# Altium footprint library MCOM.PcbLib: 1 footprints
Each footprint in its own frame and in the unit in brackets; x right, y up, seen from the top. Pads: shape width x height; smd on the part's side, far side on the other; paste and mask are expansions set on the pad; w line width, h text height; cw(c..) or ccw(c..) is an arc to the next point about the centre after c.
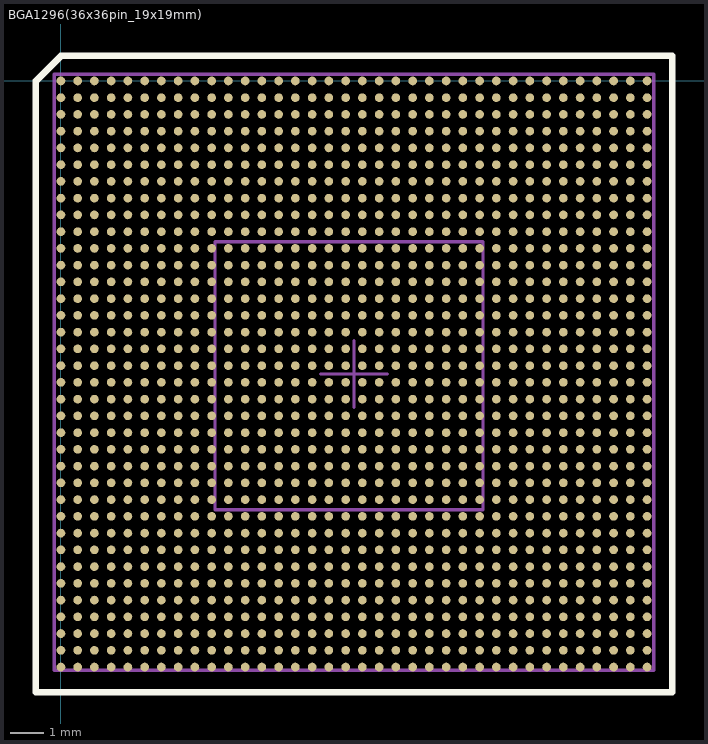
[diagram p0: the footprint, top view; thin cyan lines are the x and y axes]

## BGA1296(36x36pin_19x19mm) [mm]
height 2.5
pads (1296):
  round 0.26 smd mask+0.06: A1(0,0) A2(0.5,0) A3(1,0) A4(1.5,0) A5(2,0) A6(2.5,0) A7(3,0) A8(3.5,0) A9(4,0) A10(4.5,0) A11(5,0) A12(5.5,0) A13(6,0) A14(6.5,0) A15(7,0) A16(7.5,0) A17(8,0) A18(8.5,0) A19(9,0) A20(9.5,0) A21(10,0) A22(10.5,0) A23(11,0) A24(11.5,0) A25(12,0) A26(12.5,0) A27(13,0) A28(13.5,0) A29(14,0) A30(14.5,0) A31(15,0) A32(15.5,0) A33(16,0) A34(16.5,0) A35(17,0) A36(17.5,0) AA1(0,-10) AA2(0.5,-10) AA3(1,-10) AA4(1.5,-10) AA5(2,-10) AA6(2.5,-10) AA7(3,-10) AA8(3.5,-10) AA9(4,-10) AA10(4.5,-10) AA11(5,-10) AA12(5.5,-10) AA13(6,-10) AA14(6.5,-10) AA15(7,-10) AA16(7.5,-10) AA17(8,-10) AA18(8.5,-10) AA19(9,-10) AA20(9.5,-10) AA21(10,-10) AA22(10.5,-10) AA23(11,-10) AA24(11.5,-10) AA25(12,-10) AA26(12.5,-10) AA27(13,-10) AA28(13.5,-10) AA29(14,-10) AA30(14.5,-10) AA31(15,-10) AA32(15.5,-10) AA33(16,-10) AA34(16.5,-10) AA35(17,-10) AA36(17.5,-10) AB1(0,-10.5) AB2(0.5,-10.5) AB3(1,-10.5) AB4(1.5,-10.5) AB5(2,-10.5) AB6(2.5,-10.5) AB7(3,-10.5) AB8(3.5,-10.5) AB9(4,-10.5) AB10(4.5,-10.5) AB11(5,-10.5) AB12(5.5,-10.5) AB13(6,-10.5) AB14(6.5,-10.5) AB15(7,-10.5) AB16(7.5,-10.5) AB17(8,-10.5) AB18(8.5,-10.5) AB19(9,-10.5) AB20(9.5,-10.5) AB21(10,-10.5) AB22(10.5,-10.5) AB23(11,-10.5) AB24(11.5,-10.5) AB25(12,-10.5) AB26(12.5,-10.5) AB27(13,-10.5) AB28(13.5,-10.5) AB29(14,-10.5) AB30(14.5,-10.5) AB31(15,-10.5) AB32(15.5,-10.5) AB33(16,-10.5) AB34(16.5,-10.5) AB35(17,-10.5) AB36(17.5,-10.5) AC1(0,-11) AC2(0.5,-11) AC3(1,-11) AC4(1.5,-11) AC5(2,-11) AC6(2.5,-11) AC7(3,-11) AC8(3.5,-11) AC9(4,-11) AC10(4.5,-11) AC11(5,-11) AC12(5.5,-11) AC13(6,-11) AC14(6.5,-11) AC15(7,-11) AC16(7.5,-11) AC17(8,-11) AC18(8.5,-11) AC19(9,-11) AC20(9.5,-11) AC21(10,-11) AC22(10.5,-11) AC23(11,-11) AC24(11.5,-11) AC25(12,-11) AC26(12.5,-11) AC27(13,-11) AC28(13.5,-11) AC29(14,-11) AC30(14.5,-11) AC31(15,-11) AC32(15.5,-11) AC33(16,-11) AC34(16.5,-11) AC35(17,-11) AC36(17.5,-11) AD1(0,-11.5) AD2(0.5,-11.5) AD3(1,-11.5) AD4(1.5,-11.5) AD5(2,-11.5) AD6(2.5,-11.5) AD7(3,-11.5) AD8(3.5,-11.5) AD9(4,-11.5) AD10(4.5,-11.5) AD11(5,-11.5) AD12(5.5,-11.5) AD13(6,-11.5) AD14(6.5,-11.5) AD15(7,-11.5) AD16(7.5,-11.5) AD17(8,-11.5) AD18(8.5,-11.5) AD19(9,-11.5) AD20(9.5,-11.5) AD21(10,-11.5) AD22(10.5,-11.5) AD23(11,-11.5) AD24(11.5,-11.5) AD25(12,-11.5) AD26(12.5,-11.5) AD27(13,-11.5) AD28(13.5,-11.5) AD29(14,-11.5) AD30(14.5,-11.5) AD31(15,-11.5) AD32(15.5,-11.5) AD33(16,-11.5) AD34(16.5,-11.5) AD35(17,-11.5) AD36(17.5,-11.5) AE1(0,-12) AE2(0.5,-12) AE3(1,-12) AE4(1.5,-12) AE5(2,-12) AE6(2.5,-12) AE7(3,-12) AE8(3.5,-12) AE9(4,-12) AE10(4.5,-12) AE11(5,-12) AE12(5.5,-12) AE13(6,-12) AE14(6.5,-12) AE15(7,-12) AE16(7.5,-12) AE17(8,-12) AE18(8.5,-12) AE19(9,-12) AE20(9.5,-12) AE21(10,-12) AE22(10.5,-12) AE23(11,-12) AE24(11.5,-12) AE25(12,-12) AE26(12.5,-12) AE27(13,-12) AE28(13.5,-12) AE29(14,-12) AE30(14.5,-12) AE31(15,-12) AE32(15.5,-12) AE33(16,-12) AE34(16.5,-12) AE35(17,-12) AE36(17.5,-12) AF1(0,-12.5) AF2(0.5,-12.5) AF3(1,-12.5) AF4(1.5,-12.5) AF5(2,-12.5) AF6(2.5,-12.5) AF7(3,-12.5) AF8(3.5,-12.5) AF9(4,-12.5) AF10(4.5,-12.5) AF11(5,-12.5) AF12(5.5,-12.5) AF13(6,-12.5) AF14(6.5,-12.5) AF15(7,-12.5) AF16(7.5,-12.5) AF17(8,-12.5) AF18(8.5,-12.5) AF19(9,-12.5) AF20(9.5,-12.5) AF21(10,-12.5) AF22(10.5,-12.5) AF23(11,-12.5) AF24(11.5,-12.5) AF25(12,-12.5) AF26(12.5,-12.5) AF27(13,-12.5) AF28(13.5,-12.5) AF29(14,-12.5) AF30(14.5,-12.5) AF31(15,-12.5) AF32(15.5,-12.5) AF33(16,-12.5) AF34(16.5,-12.5) AF35(17,-12.5) AF36(17.5,-12.5) AG1(0,-13) AG2(0.5,-13) AG3(1,-13) AG4(1.5,-13) AG5(2,-13) AG6(2.5,-13) AG7(3,-13) AG8(3.5,-13) AG9(4,-13) AG10(4.5,-13) AG11(5,-13) AG12(5.5,-13) AG13(6,-13) AG14(6.5,-13) AG15(7,-13) AG16(7.5,-13) AG17(8,-13) AG18(8.5,-13) AG19(9,-13) AG20(9.5,-13) AG21(10,-13) AG22(10.5,-13) AG23(11,-13) AG24(11.5,-13) AG25(12,-13) AG26(12.5,-13) AG27(13,-13) AG28(13.5,-13) AG29(14,-13) AG30(14.5,-13) AG31(15,-13) AG32(15.5,-13) AG33(16,-13) AG34(16.5,-13) AG35(17,-13) AG36(17.5,-13) AH1(0,-13.5) AH2(0.5,-13.5) AH3(1,-13.5) AH4(1.5,-13.5) AH5(2,-13.5) AH6(2.5,-13.5) AH7(3,-13.5) AH8(3.5,-13.5) AH9(4,-13.5) AH10(4.5,-13.5) AH11(5,-13.5) AH12(5.5,-13.5) AH13(6,-13.5) AH14(6.5,-13.5) AH15(7,-13.5) AH16(7.5,-13.5) AH17(8,-13.5) AH18(8.5,-13.5) AH19(9,-13.5) AH20(9.5,-13.5) AH21(10,-13.5) AH22(10.5,-13.5) AH23(11,-13.5) AH24(11.5,-13.5) AH25(12,-13.5) AH26(12.5,-13.5) AH27(13,-13.5) AH28(13.5,-13.5) AH29(14,-13.5) AH30(14.5,-13.5) AH31(15,-13.5) AH32(15.5,-13.5) AH33(16,-13.5) AH34(16.5,-13.5) AH35(17,-13.5) AH36(17.5,-13.5) AJ1(0,-14) AJ2(0.5,-14) AJ3(1,-14) AJ4(1.5,-14) AJ5(2,-14) AJ6(2.5,-14) AJ7(3,-14) AJ8(3.5,-14) AJ9(4,-14) AJ10(4.5,-14) AJ11(5,-14) AJ12(5.5,-14) AJ13(6,-14) AJ14(6.5,-14) AJ15(7,-14) AJ16(7.5,-14) AJ17(8,-14) AJ18(8.5,-14) AJ19(9,-14) AJ20(9.5,-14) AJ21(10,-14) AJ22(10.5,-14) AJ23(11,-14) AJ24(11.5,-14) AJ25(12,-14) AJ26(12.5,-14) AJ27(13,-14) AJ28(13.5,-14) AJ29(14,-14) AJ30(14.5,-14) AJ31(15,-14) AJ32(15.5,-14) AJ33(16,-14) AJ34(16.5,-14) AJ35(17,-14) AJ36(17.5,-14) AK1(0,-14.5) AK2(0.5,-14.5) AK3(1,-14.5) AK4(1.5,-14.5) AK5(2,-14.5) AK6(2.5,-14.5) AK7(3,-14.5) AK8(3.5,-14.5) AK9(4,-14.5) AK10(4.5,-14.5) AK11(5,-14.5) AK12(5.5,-14.5) AK13(6,-14.5) AK14(6.5,-14.5) AK15(7,-14.5) AK16(7.5,-14.5) AK17(8,-14.5) AK18(8.5,-14.5) AK19(9,-14.5) AK20(9.5,-14.5) AK21(10,-14.5) AK22(10.5,-14.5) AK23(11,-14.5) AK24(11.5,-14.5) AK25(12,-14.5) AK26(12.5,-14.5) AK27(13,-14.5) AK28(13.5,-14.5) AK29(14,-14.5) AK30(14.5,-14.5) AK31(15,-14.5) AK32(15.5,-14.5) AK33(16,-14.5) AK34(16.5,-14.5) AK35(17,-14.5) AK36(17.5,-14.5) AL1(0,-15) AL2(0.5,-15) AL3(1,-15) AL4(1.5,-15) AL5(2,-15) AL6(2.5,-15) AL7(3,-15) AL8(3.5,-15) AL9(4,-15) AL10(4.5,-15) AL11(5,-15) AL12(5.5,-15) AL13(6,-15) AL14(6.5,-15) AL15(7,-15) AL16(7.5,-15) AL17(8,-15) AL18(8.5,-15) AL19(9,-15) AL20(9.5,-15) AL21(10,-15) AL22(10.5,-15) AL23(11,-15) AL24(11.5,-15) AL25(12,-15) AL26(12.5,-15) AL27(13,-15) AL28(13.5,-15) AL29(14,-15) AL30(14.5,-15) AL31(15,-15) AL32(15.5,-15) AL33(16,-15) AL34(16.5,-15) AL35(17,-15) AL36(17.5,-15) AM1(0,-15.5) AM2(0.5,-15.5) AM3(1,-15.5) AM4(1.5,-15.5) AM5(2,-15.5) AM6(2.5,-15.5) AM7(3,-15.5) AM8(3.5,-15.5) AM9(4,-15.5) AM10(4.5,-15.5) AM11(5,-15.5) AM12(5.5,-15.5) AM13(6,-15.5) AM14(6.5,-15.5) AM15(7,-15.5) AM16(7.5,-15.5) AM17(8,-15.5) AM18(8.5,-15.5) AM19(9,-15.5) AM20(9.5,-15.5) AM21(10,-15.5) AM22(10.5,-15.5) AM23(11,-15.5) AM24(11.5,-15.5) AM25(12,-15.5) AM26(12.5,-15.5) AM27(13,-15.5) AM28(13.5,-15.5) AM29(14,-15.5) AM30(14.5,-15.5) AM31(15,-15.5) AM32(15.5,-15.5) AM33(16,-15.5) AM34(16.5,-15.5) AM35(17,-15.5) AM36(17.5,-15.5) AN1(0,-16) AN2(0.5,-16) AN3(1,-16) AN4(1.5,-16) AN5(2,-16) AN6(2.5,-16) AN7(3,-16) AN8(3.5,-16) AN9(4,-16) AN10(4.5,-16) AN11(5,-16) AN12(5.5,-16) AN13(6,-16) AN14(6.5,-16) AN15(7,-16) AN16(7.5,-16) AN17(8,-16) AN18(8.5,-16) AN19(9,-16) AN20(9.5,-16) AN21(10,-16) AN22(10.5,-16) AN23(11,-16) AN24(11.5,-16) AN25(12,-16) AN26(12.5,-16) AN27(13,-16) AN28(13.5,-16) AN29(14,-16) AN30(14.5,-16) AN31(15,-16) AN32(15.5,-16) AN33(16,-16) AN34(16.5,-16) AN35(17,-16) AN36(17.5,-16) AP1(0,-16.5) AP2(0.5,-16.5) AP3(1,-16.5) AP4(1.5,-16.5) AP5(2,-16.5) AP6(2.5,-16.5) AP7(3,-16.5) AP8(3.5,-16.5) AP9(4,-16.5) AP10(4.5,-16.5) AP11(5,-16.5) AP12(5.5,-16.5) AP13(6,-16.5) AP14(6.5,-16.5) AP15(7,-16.5) AP16(7.5,-16.5) AP17(8,-16.5) AP18(8.5,-16.5) AP19(9,-16.5) AP20(9.5,-16.5) AP21(10,-16.5) AP22(10.5,-16.5) AP23(11,-16.5) AP24(11.5,-16.5) AP25(12,-16.5) AP26(12.5,-16.5) AP27(13,-16.5) AP28(13.5,-16.5) AP29(14,-16.5) AP30(14.5,-16.5) AP31(15,-16.5) AP32(15.5,-16.5) AP33(16,-16.5) AP34(16.5,-16.5) AP35(17,-16.5) AP36(17.5,-16.5) AR1(0,-17) AR2(0.5,-17) AR3(1,-17) AR4(1.5,-17) AR5(2,-17) AR6(2.5,-17) AR7(3,-17) AR8(3.5,-17) AR9(4,-17) AR10(4.5,-17) AR11(5,-17) AR12(5.5,-17) AR13(6,-17) AR14(6.5,-17) AR15(7,-17) AR16(7.5,-17) AR17(8,-17) AR18(8.5,-17) AR19(9,-17) AR20(9.5,-17) AR21(10,-17) AR22(10.5,-17) AR23(11,-17) AR24(11.5,-17) AR25(12,-17) AR26(12.5,-17) AR27(13,-17) AR28(13.5,-17) AR29(14,-17) AR30(14.5,-17) AR31(15,-17) AR32(15.5,-17) AR33(16,-17) AR34(16.5,-17) AR35(17,-17) AR36(17.5,-17) AT1(0,-17.5) AT2(0.5,-17.5) AT3(1,-17.5) AT4(1.5,-17.5) AT5(2,-17.5) AT6(2.5,-17.5) AT7(3,-17.5) AT8(3.5,-17.5) AT9(4,-17.5) AT10(4.5,-17.5) AT11(5,-17.5) AT12(5.5,-17.5) AT13(6,-17.5) AT14(6.5,-17.5) AT15(7,-17.5) AT16(7.5,-17.5) AT17(8,-17.5) AT18(8.5,-17.5) AT19(9,-17.5) AT20(9.5,-17.5) AT21(10,-17.5) AT22(10.5,-17.5) AT23(11,-17.5) AT24(11.5,-17.5) AT25(12,-17.5) AT26(12.5,-17.5) AT27(13,-17.5) AT28(13.5,-17.5) AT29(14,-17.5) AT30(14.5,-17.5) AT31(15,-17.5) AT32(15.5,-17.5) AT33(16,-17.5) AT34(16.5,-17.5) AT35(17,-17.5) AT36(17.5,-17.5) B1(0,-0.5) B2(0.5,-0.5) B3(1,-0.5) B4(1.5,-0.5) B5(2,-0.5) B6(2.5,-0.5) B7(3,-0.5) B8(3.5,-0.5) B9(4,-0.5) B10(4.5,-0.5) B11(5,-0.5) B12(5.5,-0.5) B13(6,-0.5) B14(6.5,-0.5) B15(7,-0.5) B16(7.5,-0.5) B17(8,-0.5) B18(8.5,-0.5) B19(9,-0.5) B20(9.5,-0.5) B21(10,-0.5) B22(10.5,-0.5) B23(11,-0.5) B24(11.5,-0.5) B25(12,-0.5) B26(12.5,-0.5) B27(13,-0.5) B28(13.5,-0.5) B29(14,-0.5) B30(14.5,-0.5) B31(15,-0.5) B32(15.5,-0.5) B33(16,-0.5) B34(16.5,-0.5) B35(17,-0.5) B36(17.5,-0.5) C1(0,-1) C2(0.5,-1) C3(1,-1) C4(1.5,-1) C5(2,-1) C6(2.5,-1) C7(3,-1) C8(3.5,-1) C9(4,-1) C10(4.5,-1) C11(5,-1) C12(5.5,-1) C13(6,-1) C14(6.5,-1) C15(7,-1) C16(7.5,-1) C17(8,-1) C18(8.5,-1) C19(9,-1) C20(9.5,-1) C21(10,-1) C22(10.5,-1) C23(11,-1) C24(11.5,-1) C25(12,-1) C26(12.5,-1) C27(13,-1) C28(13.5,-1) C29(14,-1) C30(14.5,-1) C31(15,-1) C32(15.5,-1) C33(16,-1) C34(16.5,-1) C35(17,-1) C36(17.5,-1) D1(0,-1.5) D2(0.5,-1.5) D3(1,-1.5) D4(1.5,-1.5) D5(2,-1.5) D6(2.5,-1.5) D7(3,-1.5) D8(3.5,-1.5) D9(4,-1.5) D10(4.5,-1.5) D11(5,-1.5) D12(5.5,-1.5) D13(6,-1.5) D14(6.5,-1.5) D15(7,-1.5) D16(7.5,-1.5) D17(8,-1.5) D18(8.5,-1.5) D19(9,-1.5) D20(9.5,-1.5) D21(10,-1.5) D22(10.5,-1.5) D23(11,-1.5) D24(11.5,-1.5) D25(12,-1.5) D26(12.5,-1.5) D27(13,-1.5) D28(13.5,-1.5) D29(14,-1.5) D30(14.5,-1.5) D31(15,-1.5) D32(15.5,-1.5) D33(16,-1.5) D34(16.5,-1.5) D35(17,-1.5) D36(17.5,-1.5) E1(0,-2) E2(0.5,-2) E3(1,-2) E4(1.5,-2) E5(2,-2) E6(2.5,-2) E7(3,-2) E8(3.5,-2) E9(4,-2) E10(4.5,-2) E11(5,-2) E12(5.5,-2) E13(6,-2) E14(6.5,-2) E15(7,-2) E16(7.5,-2) E17(8,-2) E18(8.5,-2) E19(9,-2) E20(9.5,-2) E21(10,-2) E22(10.5,-2) E23(11,-2) E24(11.5,-2) E25(12,-2) E26(12.5,-2) E27(13,-2) E28(13.5,-2) E29(14,-2) E30(14.5,-2) E31(15,-2) E32(15.5,-2) E33(16,-2) E34(16.5,-2) E35(17,-2) E36(17.5,-2) F1(0,-2.5) F2(0.5,-2.5) F3(1,-2.5) F4(1.5,-2.5) F5(2,-2.5) F6(2.5,-2.5) F7(3,-2.5) F8(3.5,-2.5) F9(4,-2.5) F10(4.5,-2.5) F11(5,-2.5) F12(5.5,-2.5) F13(6,-2.5) F14(6.5,-2.5) F15(7,-2.5) F16(7.5,-2.5) F17(8,-2.5) F18(8.5,-2.5) F19(9,-2.5) F20(9.5,-2.5) F21(10,-2.5) F22(10.5,-2.5) F23(11,-2.5) F24(11.5,-2.5) F25(12,-2.5) F26(12.5,-2.5) F27(13,-2.5) F28(13.5,-2.5) F29(14,-2.5) F30(14.5,-2.5) F31(15,-2.5) F32(15.5,-2.5) F33(16,-2.5) F34(16.5,-2.5) F35(17,-2.5) F36(17.5,-2.5) G1(0,-3) G2(0.5,-3) G3(1,-3) G4(1.5,-3) G5(2,-3) G6(2.5,-3) G7(3,-3) G8(3.5,-3) G9(4,-3) G10(4.5,-3) G11(5,-3) G12(5.5,-3) G13(6,-3) G14(6.5,-3) G15(7,-3) G16(7.5,-3) G17(8,-3) G18(8.5,-3) G19(9,-3) G20(9.5,-3) G21(10,-3) G22(10.5,-3) G23(11,-3) G24(11.5,-3) G25(12,-3) G26(12.5,-3) G27(13,-3) G28(13.5,-3) G29(14,-3) G30(14.5,-3) G31(15,-3) G32(15.5,-3) G33(16,-3) G34(16.5,-3) G35(17,-3) G36(17.5,-3) H1(0,-3.5) H2(0.5,-3.5) H3(1,-3.5) H4(1.5,-3.5) H5(2,-3.5) H6(2.5,-3.5) H7(3,-3.5) H8(3.5,-3.5) H9(4,-3.5) H10(4.5,-3.5) H11(5,-3.5) H12(5.5,-3.5) H13(6,-3.5) H14(6.5,-3.5) H15(7,-3.5) H16(7.5,-3.5) H17(8,-3.5) H18(8.5,-3.5) H19(9,-3.5) H20(9.5,-3.5) H21(10,-3.5) H22(10.5,-3.5) H23(11,-3.5) H24(11.5,-3.5) H25(12,-3.5) H26(12.5,-3.5) H27(13,-3.5) H28(13.5,-3.5) H29(14,-3.5) H30(14.5,-3.5) H31(15,-3.5) H32(15.5,-3.5) H33(16,-3.5) H34(16.5,-3.5) H35(17,-3.5) H36(17.5,-3.5) J1(0,-4) J2(0.5,-4) J3(1,-4) J4(1.5,-4) J5(2,-4) J6(2.5,-4) J7(3,-4) J8(3.5,-4) J9(4,-4) J10(4.5,-4) J11(5,-4) J12(5.5,-4) J13(6,-4) J14(6.5,-4) J15(7,-4) J16(7.5,-4) J17(8,-4) J18(8.5,-4) J19(9,-4) J20(9.5,-4) J21(10,-4) J22(10.5,-4) J23(11,-4) J24(11.5,-4) J25(12,-4) J26(12.5,-4) J27(13,-4) J28(13.5,-4) J29(14,-4) J30(14.5,-4) J31(15,-4) J32(15.5,-4) J33(16,-4) J34(16.5,-4) J35(17,-4) J36(17.5,-4) K1(0,-4.5) K2(0.5,-4.5) K3(1,-4.5) K4(1.5,-4.5) K5(2,-4.5) K6(2.5,-4.5) K7(3,-4.5) K8(3.5,-4.5) K9(4,-4.5) K10(4.5,-4.5) K11(5,-4.5) K12(5.5,-4.5) K13(6,-4.5) K14(6.5,-4.5) K15(7,-4.5) K16(7.5,-4.5) K17(8,-4.5) K18(8.5,-4.5) K19(9,-4.5) K20(9.5,-4.5) K21(10,-4.5) K22(10.5,-4.5) K23(11,-4.5) K24(11.5,-4.5) K25(12,-4.5) K26(12.5,-4.5) K27(13,-4.5) K28(13.5,-4.5) K29(14,-4.5) K30(14.5,-4.5) K31(15,-4.5) K32(15.5,-4.5) K33(16,-4.5) K34(16.5,-4.5) K35(17,-4.5) K36(17.5,-4.5) L1(0,-5) L2(0.5,-5) L3(1,-5) L4(1.5,-5) L5(2,-5) L6(2.5,-5) L7(3,-5) L8(3.5,-5) L9(4,-5) L10(4.5,-5) L11(5,-5) L12(5.5,-5) L13(6,-5) L14(6.5,-5) L15(7,-5) L16(7.5,-5) L17(8,-5) L18(8.5,-5) L19(9,-5) L20(9.5,-5) L21(10,-5) L22(10.5,-5) L23(11,-5) L24(11.5,-5) L25(12,-5) L26(12.5,-5) L27(13,-5) L28(13.5,-5) L29(14,-5) L30(14.5,-5) L31(15,-5) L32(15.5,-5) L33(16,-5) L34(16.5,-5) L35(17,-5) L36(17.5,-5) M1(0,-5.5) M2(0.5,-5.5) M3(1,-5.5) M4(1.5,-5.5) M5(2,-5.5) M6(2.5,-5.5) M7(3,-5.5) M8(3.5,-5.5) M9(4,-5.5) M10(4.5,-5.5) M11(5,-5.5) M12(5.5,-5.5) M13(6,-5.5) M14(6.5,-5.5) M15(7,-5.5) M16(7.5,-5.5) M17(8,-5.5) M18(8.5,-5.5) M19(9,-5.5) M20(9.5,-5.5) M21(10,-5.5) M22(10.5,-5.5) M23(11,-5.5) M24(11.5,-5.5) M25(12,-5.5) M26(12.5,-5.5) M27(13,-5.5) M28(13.5,-5.5) M29(14,-5.5) M30(14.5,-5.5) M31(15,-5.5) M32(15.5,-5.5) M33(16,-5.5) M34(16.5,-5.5) M35(17,-5.5) M36(17.5,-5.5) N1(0,-6) N2(0.5,-6) N3(1,-6) N4(1.5,-6) N5(2,-6) N6(2.5,-6) N7(3,-6) N8(3.5,-6) N9(4,-6) N10(4.5,-6) N11(5,-6) N12(5.5,-6) N13(6,-6) N14(6.5,-6) N15(7,-6) N16(7.5,-6) N17(8,-6) N18(8.5,-6) N19(9,-6) N20(9.5,-6) N21(10,-6) N22(10.5,-6) N23(11,-6) N24(11.5,-6) N25(12,-6) N26(12.5,-6) N27(13,-6) N28(13.5,-6) N29(14,-6) N30(14.5,-6) N31(15,-6) N32(15.5,-6) N33(16,-6) N34(16.5,-6) N35(17,-6) N36(17.5,-6) P1(0,-6.5) P2(0.5,-6.5) P3(1,-6.5) P4(1.5,-6.5) P5(2,-6.5) P6(2.5,-6.5) P7(3,-6.5) P8(3.5,-6.5) P9(4,-6.5) P10(4.5,-6.5) P11(5,-6.5) P12(5.5,-6.5) P13(6,-6.5) P14(6.5,-6.5) P15(7,-6.5) P16(7.5,-6.5) P17(8,-6.5) P18(8.5,-6.5) P19(9,-6.5) P20(9.5,-6.5) P21(10,-6.5) P22(10.5,-6.5) P23(11,-6.5) P24(11.5,-6.5) P25(12,-6.5) P26(12.5,-6.5) P27(13,-6.5) P28(13.5,-6.5) P29(14,-6.5) P30(14.5,-6.5) P31(15,-6.5) P32(15.5,-6.5) P33(16,-6.5) P34(16.5,-6.5) P35(17,-6.5) P36(17.5,-6.5) R1(0,-7) R2(0.5,-7) R3(1,-7) R4(1.5,-7) R5(2,-7) R6(2.5,-7) R7(3,-7) R8(3.5,-7) R9(4,-7) R10(4.5,-7) R11(5,-7) R12(5.5,-7) R13(6,-7) R14(6.5,-7) R15(7,-7) R16(7.5,-7) R17(8,-7) R18(8.5,-7) R19(9,-7) R20(9.5,-7) R21(10,-7) R22(10.5,-7) R23(11,-7) R24(11.5,-7) R25(12,-7) R26(12.5,-7) R27(13,-7) R28(13.5,-7) R29(14,-7) R30(14.5,-7) R31(15,-7) R32(15.5,-7) R33(16,-7) R34(16.5,-7) R35(17,-7) R36(17.5,-7) T1(0,-7.5) T2(0.5,-7.5) T3(1,-7.5) T4(1.5,-7.5) T5(2,-7.5) T6(2.5,-7.5) T7(3,-7.5) T8(3.5,-7.5) T9(4,-7.5) T10(4.5,-7.5) T11(5,-7.5) T12(5.5,-7.5) T13(6,-7.5) T14(6.5,-7.5) T15(7,-7.5) T16(7.5,-7.5) T17(8,-7.5) T18(8.5,-7.5) T19(9,-7.5) T20(9.5,-7.5) T21(10,-7.5) T22(10.5,-7.5) T23(11,-7.5) T24(11.5,-7.5) T25(12,-7.5) T26(12.5,-7.5) T27(13,-7.5) T28(13.5,-7.5) T29(14,-7.5) T30(14.5,-7.5) T31(15,-7.5) T32(15.5,-7.5) T33(16,-7.5) T34(16.5,-7.5) T35(17,-7.5) T36(17.5,-7.5) U1(0,-8) U2(0.5,-8) U3(1,-8) U4(1.5,-8) U5(2,-8) U6(2.5,-8) U7(3,-8) U8(3.5,-8) U9(4,-8) U10(4.5,-8) U11(5,-8) U12(5.5,-8) U13(6,-8) U14(6.5,-8) U15(7,-8) U16(7.5,-8) U17(8,-8) U18(8.5,-8) U19(9,-8) U20(9.5,-8) U21(10,-8) U22(10.5,-8) U23(11,-8) U24(11.5,-8) U25(12,-8) U26(12.5,-8) U27(13,-8) U28(13.5,-8) U29(14,-8) U30(14.5,-8) U31(15,-8) U32(15.5,-8) U33(16,-8) U34(16.5,-8) U35(17,-8) U36(17.5,-8) V1(0,-8.5) V2(0.5,-8.5) V3(1,-8.5) V4(1.5,-8.5) V5(2,-8.5) V6(2.5,-8.5) V7(3,-8.5) V8(3.5,-8.5) V9(4,-8.5) V10(4.5,-8.5) V11(5,-8.5) V12(5.5,-8.5) V13(6,-8.5) V14(6.5,-8.5) V15(7,-8.5) V16(7.5,-8.5) V17(8,-8.5) V18(8.5,-8.5) V19(9,-8.5) V20(9.5,-8.5) V21(10,-8.5) V22(10.5,-8.5) V23(11,-8.5) V24(11.5,-8.5) V25(12,-8.5) V26(12.5,-8.5) V27(13,-8.5) V28(13.5,-8.5) V29(14,-8.5) V30(14.5,-8.5) V31(15,-8.5) V32(15.5,-8.5) V33(16,-8.5) V34(16.5,-8.5) V35(17,-8.5) V36(17.5,-8.5) W1(0,-9) W2(0.5,-9) W3(1,-9) W4(1.5,-9) W5(2,-9) W6(2.5,-9) W7(3,-9) W8(3.5,-9) W9(4,-9) W10(4.5,-9) W11(5,-9) W12(5.5,-9) W13(6,-9) W14(6.5,-9) W15(7,-9) W16(7.5,-9) W17(8,-9) W18(8.5,-9) W19(9,-9) W20(9.5,-9) W21(10,-9) W22(10.5,-9) W23(11,-9) W24(11.5,-9) W25(12,-9) W26(12.5,-9) W27(13,-9) W28(13.5,-9) W29(14,-9) W30(14.5,-9) W31(15,-9) W32(15.5,-9) W33(16,-9) W34(16.5,-9) W35(17,-9) W36(17.5,-9) Y1(0,-9.5) Y2(0.5,-9.5) Y3(1,-9.5) Y4(1.5,-9.5) Y5(2,-9.5) Y6(2.5,-9.5) Y7(3,-9.5) Y8(3.5,-9.5) Y9(4,-9.5) Y10(4.5,-9.5) Y11(5,-9.5) Y12(5.5,-9.5) Y13(6,-9.5) Y14(6.5,-9.5) Y15(7,-9.5) Y16(7.5,-9.5) Y17(8,-9.5) Y18(8.5,-9.5) Y19(9,-9.5) Y20(9.5,-9.5) Y21(10,-9.5) Y22(10.5,-9.5) Y23(11,-9.5) Y24(11.5,-9.5) Y25(12,-9.5) Y26(12.5,-9.5) Y27(13,-9.5) Y28(13.5,-9.5) Y29(14,-9.5) Y30(14.5,-9.5) Y31(15,-9.5) Y32(15.5,-9.5) Y33(16,-9.5) Y34(16.5,-9.5) Y35(17,-9.5) Y36(17.5,-9.5)
Top Overlay:
  lines w0.2: -0.75,-18.25 18.25,-18.25 18.25,0.75 0,0.75 -0.75,0 -0.75,-18.25
Mechanical 13:
  lines w0.1: 4.6,-12.8 12.6,-12.8 12.6,-4.8 4.6,-4.8 4.6,-12.8
Mechanical 15:
  lines w0.1: 7.75,-8.75 9.75,-8.75 ; 8.75,-9.75 8.75,-7.75 ; -0.2,-17.6 17.7,-17.6 17.7,0.2 -0.2,0.2 -0.2,-17.6
3D body: height 1.15, standoff 0, extent -0.751,-18.251 18.251,0.751
3D body: height 1.65, standoff 1.15, extent -0.199,-17.599 17.699,0.199
3D body: height 2.5, standoff 1.65, extent 3.6,-13.8 13.6,-3.8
